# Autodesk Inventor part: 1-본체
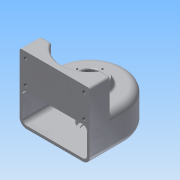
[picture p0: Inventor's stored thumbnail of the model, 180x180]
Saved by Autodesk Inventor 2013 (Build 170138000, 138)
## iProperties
Created: 2015-02
Part Number: 1-본체
Material: 알루미늄 6061
Document SubType Name: Modeling
Designer: Administrator
Density: 2.40731 g/cm^3
Mass: 511.027 g
Surface Area: 707.302 cm^2
Volume: 212.281 cm^3
Author: Administrator
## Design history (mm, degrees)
sketch "스케치1"
  geometry: L1 (50, -25)-(-50, -25); L2 (-50, -25)-(-50, 25); L3 (-50, 25)-(50, 25); L4 (50, 25)-(50, -25); L5 (50, -25)-(-50, 25); L6 (-50, -25)-(50, 25); C1 r 50 at (0, 25); 2 further points
  constraints: 12 end point, 3 midpoint, 2 parallel, 1 centre point, 1 horizontal, 1 perpendicular, 1 vertical alignment
  dimensions: "d0" = 50 distance of L1.end L2.end; "d2" = 100 distance of L1.start L1.end; "d3" = 50 radius of C1; "d4" = 50 distance from line of L1 C1.centre
extrude "돌출1" new body sketch "스케치1" distance "d5" = 50; taper "d6" = 0 deg
sketch "스케치2"
  geometry: L1 (-50, 25)-(-50, -25) reference; L2 (-50, -25)-(50, -25) reference; L3 (50, -25)-(50, 25) reference; L4 (-50, 5)-(50, 5); 1 further point
  constraints: 2 end point, 2 point on line, 1 perpendicular
  dimensions: "d7" = 30 distance between parallel lines of L2 L4
extrude "돌출2" join sketch "스케치2" distance "d8" = 45; taper "d9" = 0 deg
node "작업 평면1"
sketch "스케치3"
  geometry: L1 (-50, -25)-(50, -25) reference; C1 r 40 at (0, 25); 1 further point
  constraints: 1 centre point, 1 vertical alignment
  dimensions: "d11" = 50 distance from line of C1.centre L1; "d12" = 40 radius of C1
extrude "돌출3" cut sketch "스케치3" distance "d13" = 50; taper "d14" = 0 deg
sketch "스케치4"
  geometry: C1 r 25 at (0, 25); A1 r 40 centre (0, 25) between (-34.641, 5) and (34.641, 5) reference; 1 further point
  constraints: 1 centre point, 1 coincident
  dimensions: "d15" = 50 diameter of C1
extrude "돌출4" join sketch "스케치4" distance "d17" = 10; taper "d18" = -20 deg
sketch "스케치5"
  geometry: C1 r 20 at (0, 25); A1 r 50 centre (0, 25) between (50, 25) and (-50, 25) reference; 1 further point
  constraints: 1 centre point, 1 coincident
  dimensions: "d19" = 40 diameter of C1
extrude "돌출5" join sketch "스케치5" distance "d21" = 9; taper "d22" = 0 deg
node "작업 평면2"
sketch "스케치6"
  geometry: L1 (50, 25)-(50, -25) reference; L2 (-50, -25)-(-50, 25) reference; L3 (50, -25)-(-50, -25) reference; L4 (46, 25)-(46, -21); L5 (-46, -21)-(-46, 25); L6 (46, -21)-(46, -25); L7 (-46, -21)-(-46, -25); A1 r 50 centre (0, 25) between (50, 25) and (-50, 25) reference; A2 r 46 centre (0, 25) between (46, 25) and (-46, 25); 1 further point
  constraints: 8 end point, 2 perpendicular, 2 point on circle, 2 point on line, 1 centre point, 1 tangent, 1 other
  dimensions: "d25" = 46 radius of A2; "d26" = 90 deg angle of L5 L3; "d27" = 4 distance from line of L4.end L3; "d28" = 4 distance from line of L5.start L3
extrude "돌출6" cut sketch "스케치6" stored distance "d29" = 42; taper "d30" = 0 deg
sketch "스케치7"
  geometry: L1 (100, 0)-(0, 0) reference; L2 (0, 95)-(100, 95) reference; L3 (91.75, 86)-(8.25, 86); L4 (8.25, 86)-(8.25, 53); L5 (8.25, 53)-(91.75, 53); L6 (91.75, 53)-(91.75, 86); 7 further points
  constraints: 8 end point, 4 coincident, 2 midpoint, 2 parallel, 1 horizontal, 1 perpendicular, 1 vertical alignment
  dimensions: "d31" = 83.5 distance of L3.start L3.end; "d33" = 33 distance of L5.end L3.start; "d34" = 9 distance between parallel lines of L3 L2
hole "구멍1" sketch "스케치7" at (91.75, 86), (8.25, 86), (8.25, 53), (91.75, 53) diameter "d35" = 5.134; stored, may be unused: countersink angle "d39" = 90 deg, drill point angle "d41" = 118 deg; dims "d36" = 10, "d37" = 4, "d38" = 2, "d40" = 13
hole "구멍2" diameter "d44" = 20; stored, may be unused: countersink angle "d48" = 90 deg, drill point angle "d50" = 0 deg; dims "d42" = 10, "d43" = 10, "d45" = 20, "d46" = 28, "d47" = 10, "d49" = 14
sketch "스케치8"
  geometry: A1 r 46 centre (0, 25) between (46, 25) and (-46, 25) reference; 1 further point
hole "구멍3" sketch "스케치8" at (0, 25) diameter "d51" = 20; stored, may be unused: countersink angle "d55" = 90 deg, drill point angle "d57" = 0 deg; dims "d52" = 6, "d53" = 28, "d54" = 8, "d56" = 10
sketch "스케치9"
  geometry: C1 r 14 at (0, 0) reference; C2 r 21.36 at (0, 0) reference; A1 r 18 centre (0, 0) between (0, 18) and (0, -18); 3 further points
  constraints: 4 point on circle, 2 horizontal alignment, 2 vertical alignment, 1 centre point, 1 coincident
  dimensions: "d58" = 36 diameter of A1
node "작업 평면3"
sketch "스케치10"
  geometry: L1 (-100, 0)-(0, 0) reference; 3 further points
  constraints: 1 midpoint, 1 vertical alignment, 1 other
  dimensions: "d61" = 25 distance of point (-50, 0) point (-50, 25)
feature "엠보싱1" sketch "스케치10" dims "d0" = 50, "d2" = 100, "d3" = 50, "d4" = 50, "d11" = 50, "d12" = 40, "d62" = 0.5, "d63" = 0
fillet "모깎기1" dims "d64" = 10
fillet "모깎기2" dims "d65" = 6
fillet "모깎기3" dims "d66" = 0.3
chamfer "모따기1" distance "d67" = 1; stored, may be unused: second distance "d68" = 2, angle "d69" = 45 deg
fillet "모깎기4" dims "d70" = 3
fillet "모깎기5" dims "d71" = 3
fillet "모깎기6" dims "d72" = 3
fillet "모깎기7" dims "d73" = 3
fillet "모깎기8" dims "d74" = 3
sketch "스케치11"
  geometry: C1 r 21.36 at (0, 0) reference; C2 r 15 at (0, 0) reference; A1 r 18 centre (0, 0) between (0, 18) and (-18, 0); 3 further points
  constraints: 4 point on circle, 2 horizontal alignment, 2 vertical alignment, 1 centre point, 1 coincident
  dimensions: "d75" = 36 diameter of A1
hole "구멍4" sketch "스케치11" at (0, 18), (-18, 0), (0, -18), (18, 0) diameter "d77" = 2.459; stored, may be unused: countersink angle "d81" = 90 deg, drill point angle "d83" = 118 deg; dims "d78" = 6, "d79" = 4, "d80" = 2, "d82" = 9
node "솔리드1"
other parameters: "d10" = 0, "d23" = 25
